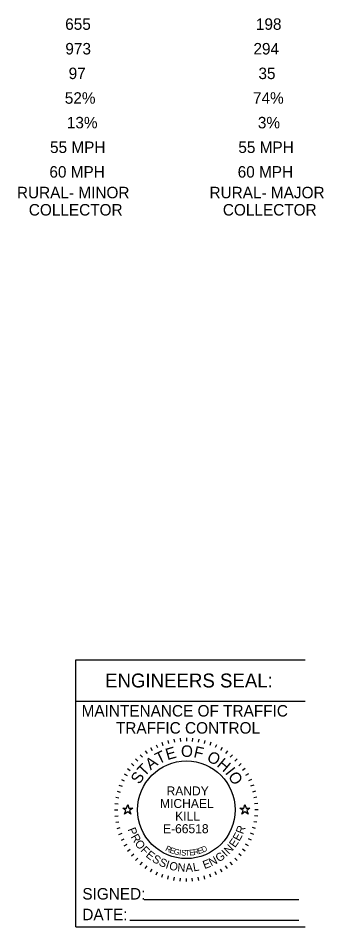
# Model space of a CAD drawing. Extents: x -17 to 88, y -5 to 22.
# Drawn here: x -5.47 to -1.74, y -1.6 to 9.47 of the extents above; entities that cross this region are included whole.
import ezdxf

# ---------------------------------------------------------------- set-up
doc = ezdxf.new("R2010")
doc.units = 0
doc.layers.add('SH_Data', color=7, linetype='Continuous')
doc.layers.add('TX_P_10', color=7, linetype='Continuous')

msp = doc.modelspace()

# ---------------------------------------------------------------- linework, layer by layer
at = {"layer": 'SH_Data'}
for p, q in [((-4.771, -1.599), (-4.771, 1.651)), ((-4.771, 1.651), (-1.971, 1.651)), ((-4.771, 1.151), (-1.971, 1.151)), ((-3.649, 0.671), (-3.638, 0.633)), ((-3.574, 0.688), (-3.567, 0.649)), ((-3.499, 0.698), (-3.495, 0.658)), ((-3.422, 0.701), (-3.422, 0.661)), ((-3.346, 0.698), (-3.35, 0.658)), ((-3.27, 0.688), (-3.277, 0.649)), ((-3.196, 0.671), (-3.206, 0.633)), ((-3.86, 0.584), (-3.84, 0.549)), ((-3.792, 0.619), (-3.775, 0.583)), ((-3.722, 0.649), (-3.708, 0.611)), ((-3.123, 0.649), (-3.137, 0.611)), ((-3.053, 0.619), (-3.069, 0.583)), ((-2.985, 0.584), (-3.005, 0.549)), ((-4.041, 0.445), (-4.013, 0.417)), ((-3.985, 0.497), (-3.959, 0.466)), ((-3.924, 0.543), (-3.901, 0.51)), ((-2.921, 0.543), (-2.943, 0.51)), ((-2.86, 0.497), (-2.886, 0.466)), ((-2.804, 0.445), (-2.832, 0.417)), ((-4.093, 0.389), (-4.062, 0.363)), ((-2.752, 0.389), (-2.783, 0.363)), ((-4.18, 0.264), (-4.146, 0.244)), ((-4.139, 0.328), (-4.106, 0.305)), ((-2.706, 0.328), (-2.738, 0.305)), ((-2.665, 0.264), (-2.699, 0.244)), ((-4.245, 0.126), (-4.207, 0.112)), ((-4.215, 0.196), (-4.179, 0.179)), ((-2.629, 0.196), (-2.666, 0.179)), ((-2.6, 0.126), (-2.638, 0.112)), ((-4.268, 0.053), (-4.229, 0.042)), ((-2.577, 0.053), (-2.616, 0.042)), ((-4.294, -0.097), (-4.254, -0.101)), ((-4.284, -0.022), (-4.245, -0.029)), ((-2.561, -0.022), (-2.6, -0.029)), ((-2.551, -0.097), (-2.591, -0.101)), ((-4.297, -0.174), (-4.257, -0.174)), ((-2.547, -0.174), (-2.587, -0.174)), ((-4.294, -0.25), (-4.254, -0.246)), ((-4.284, -0.326), (-4.245, -0.319)), ((-2.561, -0.326), (-2.6, -0.319)), ((-2.551, -0.25), (-2.591, -0.246)), ((-4.268, -0.4), (-4.229, -0.39)), ((-2.577, -0.4), (-2.616, -0.39)), ((-4.245, -0.473), (-4.207, -0.459)), ((-4.215, -0.543), (-4.179, -0.527)), ((-2.629, -0.543), (-2.666, -0.527)), ((-2.6, -0.473), (-2.638, -0.459)), ((-4.18, -0.611), (-4.146, -0.591)), ((-4.139, -0.676), (-4.106, -0.653)), ((-2.706, -0.676), (-2.738, -0.653)), ((-2.665, -0.611), (-2.699, -0.591)), ((-4.093, -0.736), (-4.062, -0.71)), ((-4.041, -0.792), (-4.013, -0.764)), ((-2.804, -0.792), (-2.832, -0.764)), ((-2.752, -0.736), (-2.783, -0.71)), ((-3.985, -0.844), (-3.959, -0.813)), ((-3.924, -0.89), (-3.901, -0.858)), ((-2.921, -0.89), (-2.943, -0.858)), ((-2.86, -0.844), (-2.886, -0.813)), ((-3.86, -0.931), (-3.84, -0.897)), ((-3.792, -0.967), (-3.775, -0.93)), ((-3.722, -0.996), (-3.708, -0.958)), ((-3.649, -1.019), (-3.638, -0.98)), ((-3.574, -1.035), (-3.567, -0.996)), ((-3.27, -1.035), (-3.277, -0.996)), ((-3.196, -1.019), (-3.206, -0.98)), ((-3.123, -0.996), (-3.137, -0.958)), ((-3.053, -0.967), (-3.069, -0.93)), ((-2.985, -0.931), (-3.005, -0.897)), ((-3.499, -1.045), (-3.495, -1.006)), ((-3.422, -1.049), (-3.422, -1.009)), ((-3.346, -1.045), (-3.35, -1.006)), ((-3.935, -1.267), (-2.05, -1.267)), ((-4.113, -1.519), (-2.05, -1.519)), ((-4.771, -1.599), (-1.971, -1.599))]:
    msp.add_line(p, q, dxfattribs=at)
for points in [[(-4.199, -0.154), (-4.152, -0.154), (-4.137, -0.109), (-4.123, -0.154), (-4.076, -0.154), (-4.114, -0.181), (-4.099, -0.226), (-4.137, -0.198), (-4.175, -0.226), (-4.161, -0.181)], [(-2.769, -0.154), (-2.722, -0.154), (-2.707, -0.109), (-2.693, -0.154), (-2.646, -0.154), (-2.684, -0.181), (-2.669, -0.226), (-2.707, -0.198), (-2.745, -0.226), (-2.731, -0.181)]]:
    msp.add_lwpolyline(points, close=True, dxfattribs=at)
msp.add_circle((-3.422, -0.174), 0.595, dxfattribs=at)

# ---------------------------------------------------------------- texts
for s, height, p in [('ENGINEERS SEAL:', 0.17, (-4.414, 1.316)), ('MAINTENANCE OF TRAFFIC', 0.14, (-4.7, 0.962)), ('TRAFFIC CONTROL', 0.14, (-4.281, 0.754)), ('RANDY', 0.11, (-3.664, 0.001)), ('MICHAEL', 0.11, (-3.743, -0.152)), ('KILL', 0.11, (-3.559, -0.305)), ('E-66518', 0.11, (-3.707, -0.459)), ('SIGNED:', 0.14, (-4.691, -1.267)), ('DATE:', 0.14, (-4.691, -1.519))]:
    msp.add_text(s, height=height, dxfattribs=at).set_placement(p)
for s, height, rotation, p in [('E', 0.14, 15.7571, (-3.654, 0.43)), ('O', 0.14, 359.7812, (-3.488, 0.471)), ('F', 0.14, 347.4362, (-3.341, 0.468)), ('A', 0.14, 36.4747, (-3.859, 0.304)), ('T', 0.14, 25.7167, (-3.761, 0.378)), ('O', 0.14, 332.2586, (-3.183, 0.428)), ('H', 0.14, 319.9136, (-3.059, 0.362)), ('T', 0.14, 46.4344, (-3.934, 0.223)), ('I', 0.14, 308.367, (-2.956, 0.275)), ('S', 0.14, 57.1924, (-3.994, 0.128)), ('O', 0.14, 303.1491, (-2.92, 0.235)), ('P', 0.1, 291.494, (-4.14, -0.412)), ('R', 0.1, 69.2322, (-2.73, -0.478)), ('R', 0.1, 298.7311, (-4.103, -0.502)), ('O', 0.1, 306.4666, (-4.057, -0.585)), ('E', 0.1, 54.758, (-2.829, -0.642)), ('E', 0.1, 61.9951, (-2.775, -0.564)), ('F', 0.1, 314.7068, (-3.988, -0.675)), ('R', 0.07, 334.487, (-3.685, -0.669)), ('E', 0.07, 341.04, (-3.632, -0.694)), ('G', 0.07, 347.4752, (-3.581, -0.712)), ('I', 0.07, 353.7858, (-3.513, -0.727)), ('S', 0.07, 356.8926, (-3.487, -0.731)), ('T', 0.07, 3.0061, (-3.437, -0.735)), ('E', 0.07, 6.0117, (-3.383, -0.732)), ('R', 0.07, 11.9184, (-3.33, -0.726)), ('E', 0.07, 17.6836, (-3.273, -0.714)), ('D', 0.07, 23.3052, (-3.221, -0.697)), ('I', 0.1, 43.287, (-2.936, -0.752)), ('N', 0.1, 47.0224, (-2.902, -0.723)), ('E', 0.1, 321.4393, (-3.925, -0.739)), ('S', 0.1, 328.6764, (-3.848, -0.798)), ('S', 0.1, 335.9134, (-3.766, -0.847)), ('N', 0.1, 27.3113, (-3.118, -0.866)), ('G', 0.1, 35.0469, (-3.024, -0.817)), ('I', 0.1, 343.1505, (-3.682, -0.884)), ('O', 0.1, 346.8859, (-3.639, -0.899)), ('N', 0.1, 355.1261, (-3.534, -0.922)), ('A', 0.1, 2.8617, (-3.43, -0.93)), ('L', 0.1, 10.0987, (-3.333, -0.925)), ('E', 0.1, 20.0742, (-3.201, -0.897))]:
    msp.add_text(s, height=height, rotation=rotation, dxfattribs=at).set_placement(p)
at = {"layer": 'TX_P_10'}
for s, p in [('655', (-4.9, 9.327)), ('198', (-2.574, 9.327)), ('973', (-4.898, 9.027)), ('294', (-2.604, 9.027)), ('97', (-4.858, 8.727)), ('35', (-2.543, 8.727)), ('52%', (-4.905, 8.427)), ('74%', (-2.609, 8.427)), ('13%', (-4.88, 8.127)), ('3%', (-2.55, 8.127)), ('55 MPH', (-5.085, 7.827)), ('55 MPH', (-2.788, 7.827)), ('60 MPH', (-5.093, 7.527)), ('60 MPH', (-2.796, 7.527)), ('RURAL- MINOR ', (-5.489, 7.275)), ('RURAL- MAJOR ', (-3.14, 7.275)), ('COLLECTOR', (-5.344, 7.065)), ('COLLECTOR', (-2.977, 7.065))]:
    msp.add_text(s, height=0.14, dxfattribs=at).set_placement(p)

doc.saveas('drawing.dxf')
